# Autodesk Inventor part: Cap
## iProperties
Shininess: 77.0
Length Units: 11269
Angle Units: 11279
Time Units: 11290
Mass Units: 11283
Length Display Precision: 3
Angle Display Precision: 2
Created: 2002-02
Part Number: Cap
Document SubType Name: Modeling
Designer: ***
Density: 0.0
Volumn: 0.0
Area: 0.0
PropertySet Name: Model Information
Control State: 0
Master: False
Checked Out: False
Author: ***
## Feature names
1. Extrusion1
2. Extrusion2
3. Hole1
4. Hole2
5. Mirror1
6. Hole3
